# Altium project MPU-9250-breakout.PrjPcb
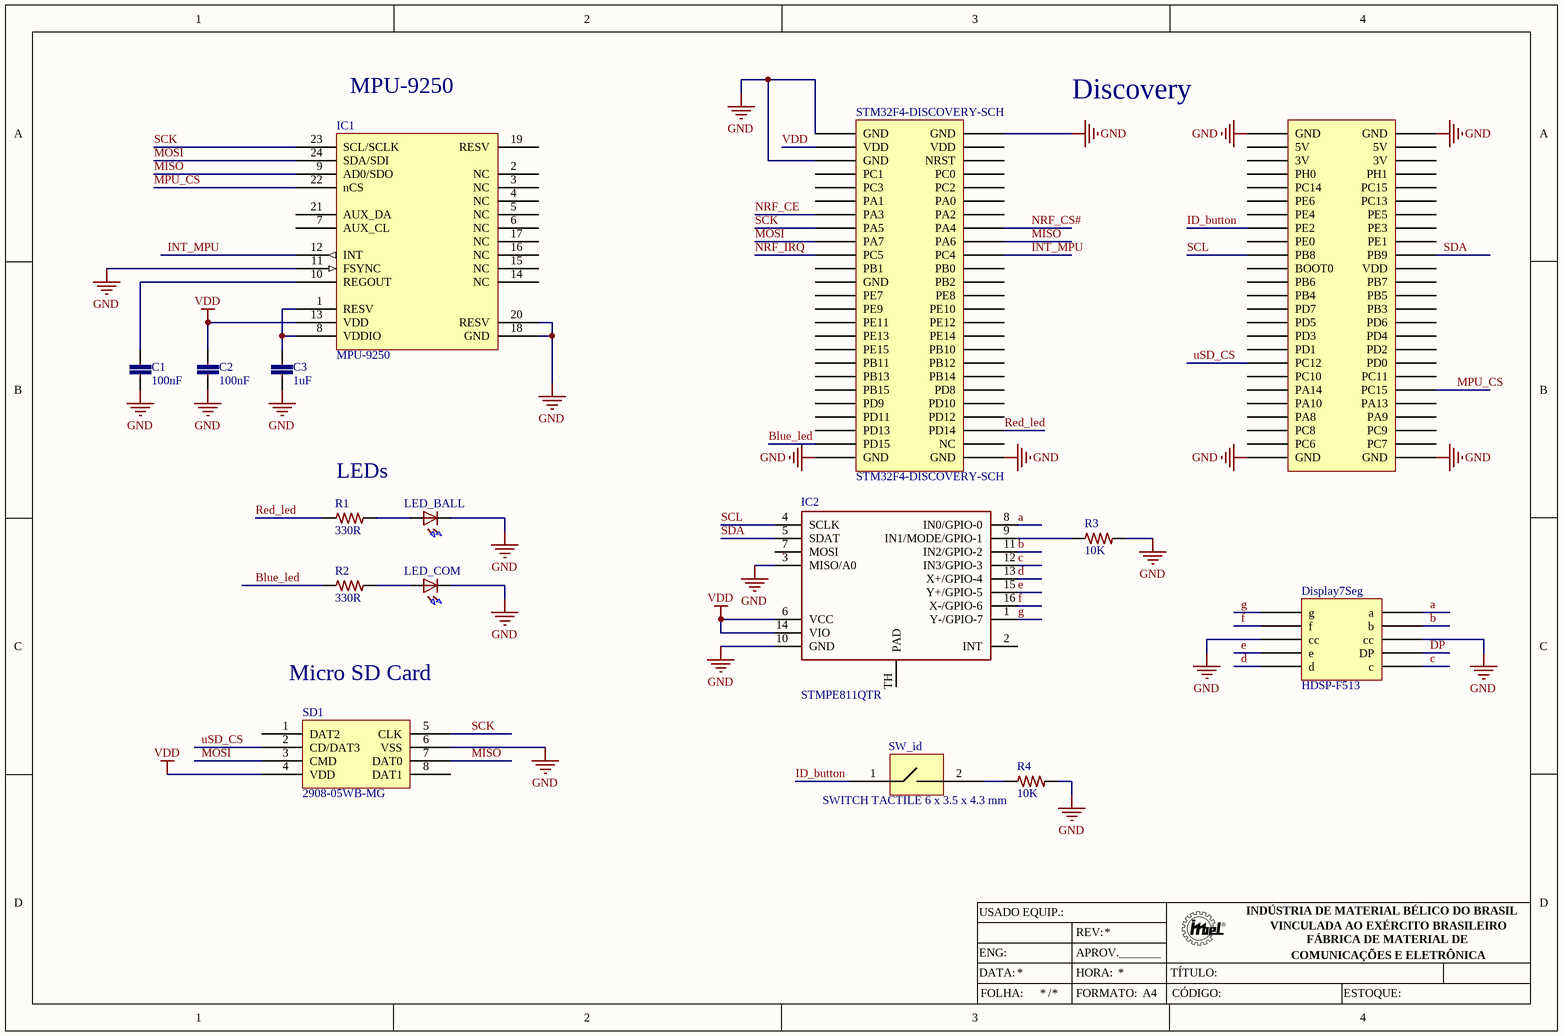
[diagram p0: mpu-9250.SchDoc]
1 sheet, 15 parts. Net scope: global (net labels, ports and power ports of the same name join across sheets).
Board file: mpu-9250.PcbDoc

## Sheet mpu-9250.SchDoc
size A4; Organization1: VINCULADA AO EXÉRCITO BRASILEIRO; Organization2: FÁBRICA DE MATERIAL DE; Organization3: COMUNICAÇÕES E ELETRÔNICA; Organization0: INDÚSTRIA DE MATERIAL BÉLICO DO BRASIL

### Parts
C1  100nF  [0402-CAP]
C2  100nF  [0402-CAP]
C3  1uF  [0402-CAP]
Display7Seg  HDSP-F513  [New footprint 1]
IC1  MPU-9250  [MPU-9250]
IC2  STMPE811QTR  [QFN16_N]
LED_BALL  LED  [LED-5MM-PCB]  (value not drawn)
LED_COM  LED  [LED-5MM-PCB]  (value not drawn)
R1  330R  [0402-RES-HD]
R2  330R  [0402-RES-HD]
R3  10K  [0402-RES-HD]
R4  10K  [0402-RES-HD]
SD1  2908-05WB-MG  [New footprint 1]
STM32F4-DISCOVERY-SCH  STM32F4-DISCOVERY-SCH  [STM32F4-DISCOVERY-PCB]
SW_id  SWITCH TACTILE 6 x 3.5 x 4.3 mm  [PCBComponent]

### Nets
GND: C1.2 C2.2 C3.2 Display7Seg.3(cc) Display7Seg.8(cc) IC1.11(FSYNC) IC1.18(GND) IC1.20(RESV) IC2.3(MISO/A0) IC2.10(GND) LED_BALL.1(K) LED_COM.1(K) R3.2 R4.2 SD1.6(VSS) STM32F4-DISCOVERY-SCH.P1_1(GND) STM32F4-DISCOVERY-SCH.P1_2(GND) STM32F4-DISCOVERY-SCH.P1_5(GND) STM32F4-DISCOVERY-SCH.P1_49(GND) STM32F4-DISCOVERY-SCH.P1_50(GND) STM32F4-DISCOVERY-SCH.P2_1(GND) STM32F4-DISCOVERY-SCH.P2_2(GND) STM32F4-DISCOVERY-SCH.P2_49(GND) STM32F4-DISCOVERY-SCH.P2_50(GND)
VDD: C2.1 IC1.13(VDD) IC2.6(VCC) IC2.14(VIO) SD1.4(VDD) STM32F4-DISCOVERY-SCH.P1_3(VDD)
a: Display7Seg.6(a) IC2.8(IN0/GPIO-0)
b: Display7Seg.7(b) IC2.11(IN2/GPIO-2)
Blue_led: R2.1 STM32F4-DISCOVERY-SCH.P1_47(PD15)
c: Display7Seg.10(c) IC2.12(IN3/GPIO-3)
d: Display7Seg.5(d) IC2.13(X+/GPIO-4)
DP: Display7Seg.9(DP)
e: Display7Seg.4(e) IC2.15(Y+/GPIO-5)
f: Display7Seg.2(f) IC2.16(X-/GPIO-6)
g: Display7Seg.1(g) IC2.1(Y-/GPIO-7)
ID_button: STM32F4-DISCOVERY-SCH.P2_15(PE2) SW_id.1
INT_MPU: IC1.12(INT) STM32F4-DISCOVERY-SCH.P1_20(PC4)
MISO: IC1.9(AD0/SDO) SD1.7(DAT0) STM32F4-DISCOVERY-SCH.P1_18(PA6)
MOSI: IC1.24(SDA/SDI) SD1.3(CMD) STM32F4-DISCOVERY-SCH.P1_17(PA7)
MPU_CS: IC1.22(nCS) STM32F4-DISCOVERY-SCH.P2_40(PC15)
NRF_CE: STM32F4-DISCOVERY-SCH.P1_13(PA3)
NRF_CS#: STM32F4-DISCOVERY-SCH.P1_16(PA4)
NRF_IRQ: STM32F4-DISCOVERY-SCH.P1_19(PC5)
Red_led: R1.1 STM32F4-DISCOVERY-SCH.P1_46(PD14)
SCK: IC1.23(SCL/SCLK) SD1.5(CLK) STM32F4-DISCOVERY-SCH.P1_15(PA5)
SCL: IC2.4(SCLK) STM32F4-DISCOVERY-SCH.P2_19(PB8)
SDA: IC2.5(SDAT) STM32F4-DISCOVERY-SCH.P2_20(PB9)
uSD_CS: SD1.2(CD/DAT3) STM32F4-DISCOVERY-SCH.P2_35(PC12)
NetC1_1: C1.1 IC1.10(REGOUT)
NetC3_1: C3.1 IC1.1(RESV) IC1.8(VDDIO)
NetIC2_9: IC2.9(IN1/MODE/GPIO-1) R3.1
NetLED_BALL_2: LED_BALL.2(A) R1.2
NetLED_COM_2: LED_COM.2(A) R2.2
NetR4_1: R4.1 SW_id.2

Not connected (* = marked no-connect by the designer): IC1 2(NC) 3(NC) 4(NC) 5(NC) 6(NC) 7(AUX_CL) 14(NC) 15(NC) 16(NC) 17(NC) 19(RESV) 21(AUX_DA); IC2 2(INT) 7(MOSI) TH(PAD); SD1 1(DAT2) 8(DAT1); STM32F4-DISCOVERY-SCH P1_6(NRST) P1_7(PC1) P1_8(PC0) P1_9(PC3) P1_10(PC2) P1_11(PA1) P1_12(PA0) P1_14(PA2) P1_21(PB1) P1_22(PB0) P1_23(GND) P1_24(PB2) P1_25(PE7) P1_26(PE8) P1_27(PE9) P1_28(PE10) P1_29(PE11) P1_30(PE12) P1_31(PE13) P1_32(PE14) P1_33(PE15) P1_34(PB10) P1_35(PB11) P1_36(PB12) P1_37(PB13) P1_38(PB14) P1_39(PB15) P1_40(PD8) P1_41(PD9) P1_42(PD10) P1_43(PD11) P1_44(PD12) P1_45(PD13) P1_48(NC) P2_3(5V) P2_4(VDD) P2_5(3V) P2_6(3V) P2_7(PH0) P2_8(PH1) P2_9(PC14) P2_10(PC15) P2_11(PE6) P2_12(PC13) P2_13(PE4) P2_14(PE5) P2_16(PE3) P2_17(PE0) P2_18(PE1) P2_21(BOOT0) P2_22(VDD) P2_23(PB6) P2_25(PB4) P2_26(PB5) P2_27(PD7) P2_28(PB3) P2_29(PD5) P2_30(PD6) P2_31(PD3) P2_32(PD4) P2_33(PD1) P2_36(PD0) P2_37(PC10) P2_38(PC11) P2_39(PA14) P2_41(PA10) P2_42(PA13) P2_43(PA8) P2_44(PA9) P2_45(PC8) P2_46(PC9) P2_47(PC6) P2_48(PC7)

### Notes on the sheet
- (near IC1) MPU-9250
- (near STM32F4-DISCOVERY-SCH) Discovery
- (near R1) LEDs
- (near SD1) Micro SD Card

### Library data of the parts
C1 C2 = CC0402-100nF-A.12: CAP CER 0.1UF 10V 20% X5R 0402; Part No: VJ0402V104ZXQPBC; Cod EMS: 05.281.006.133; Value: 100n
C3 = CC0402-1uF-5: CAP CER 1UF 6.3V 10% X5R 0402; Part No: JMK105BJ105KV-F; Cod EMS: 05.281.019.513; Value: 1u
Display7Seg = HDSP-F513-01.A.1: 7 segments display
IC1 = MPU-9250-1: IMU ACCEL/GYRO/MAG I2C/SPI 24QFN
IC2 = STMPE811QTR-6: IC TSC I/O EXPAND 8B 16QFN; Cod EMS: 05.284.001.511
LED_BALL LED_COM = LED-5MM-3: LED 5MM PTH
R1 R2 = R0402-330R-7: RES 330 OHM 1/10W 1% 0402 SMD; Part No: ERJ-2RKF3300X; Cod EMS: 05.280.029.506; Value: 330; Family Description: RESISTOR FILME ESPESSO 10R-1M / 1/10W / 1% / 0402. P/N: ERJ-2RKF....X – PANASONIC ELECTRONIC COMPONENTS.
R3 R4 = R0402-10K-11: RES 10K OHM 1/10W 1% 0402 SMD; Part No: ERJ-2RKF1002X; Cod EMS: 05.280.029.525; Family Description: RESISTOR FILME ESPESSO 10R-1M / 1/10W / 1% / 0402. P/N: ERJ-2RKF....X – PANASONIC ELECTRONIC COMPONENTS.
SD1 = 2908-05WB-MG-01.A.1: CONN MICRO SD CARD PUSH-PUSH R/A
SW_id = 95C04A3GWRT.-1: GRAYHILL TACT,GW,6X3.5,1800T&R,LF Eight, 160g Operating Force, Gull Wing, RoHS Compliant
